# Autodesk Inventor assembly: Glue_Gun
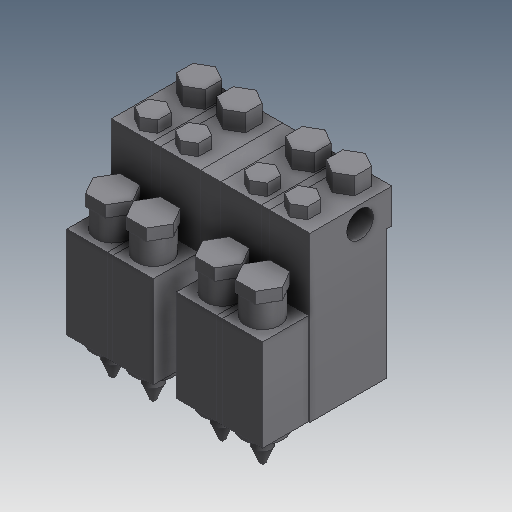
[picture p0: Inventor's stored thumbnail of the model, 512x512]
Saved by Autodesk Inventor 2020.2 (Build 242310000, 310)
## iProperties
Created: 2000-02
Part Number: Glue_Gun
Document SubType Name: Assembly
Designer: mpflueger
Mass: 4924.97 g
Surface Area: 1002.22 cm^2
Volume: 628.987 cm^3
Density: 7.83 g/cm^3
Control State: 0
Master: False
Checked Out: False
Shininess: 0.0
Length Units: 11269
Angle Units: 11279
Time Units: 11290
Mass Units: 11283
Length Display Precision: 3
Angle Display Precision: 2
Compacted: True
Dimensions: 120,6x100,8x109,7 mm
Mass: 4,925 kg
Density: 0.0
Volumn: 0.0
Area: 0.0
PropertySet Name: Model Information
Author: mpflueger
Revision Number: -
Title: Glue_Gun
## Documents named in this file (3)
- D:\07 - DEMODATEN\OTX 2019 - Dataset - UPDATE - Dez2019\Designs\07-Packing machine\A097170.iam
- D:\07 - DEMODATEN\OTX 2019 - Dataset - UPDATE - Dez2019\Designs\07-Packing machine\Parts\ADSK-011746.ipt
- D:\07 - DEMODATEN\OTX 2019 - Dataset - UPDATE - Dez2019\Designs\07-Packing machine\Parts\ADSK-011745.ipt
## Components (5 placed, 2 different names)
1. ADSK-011745:1 — Flush:1, Flush:2, Mate:1
2. ADSK-011745:2 — Flush:1, Flush:2, Flush:3, Flush:4, Mate:1, Mate:3, Flush:7, Flush:8
3. ADSK-011745:3 — Flush:3, Flush:4, Flush:5, Flush:6, Mate:2, Mate:3, Mate:4
4. ADSK-011745:4 — Flush:5, Flush:6, Mate:2
5. ADSK-011746:1 — Flush:7, Flush:8, Mate:4
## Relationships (12: Flush 8, Mate 4)
- Flush:1: ADSK-011745:1 ↔ ADSK-011745:2
- Flush:2: ADSK-011745:1 ↔ ADSK-011745:2
- Flush:3: ADSK-011745:2 ↔ ADSK-011745:3
- Flush:4: ADSK-011745:2 ↔ ADSK-011745:3
- Flush:5: ADSK-011745:3 ↔ ADSK-011745:4
- Flush:6: ADSK-011745:3 ↔ ADSK-011745:4
- Mate:1: ADSK-011745:1 ↔ ADSK-011745:2
- Mate:2: ADSK-011745:3 ↔ ADSK-011745:4
- Mate:3: ADSK-011745:2 ↔ ADSK-011745:3
- Flush:7: ADSK-011745:2 ↔ ADSK-011746:1
- Flush:8: ADSK-011745:2 ↔ ADSK-011746:1
- Mate:4: ADSK-011745:3 ↔ ADSK-011746:1
